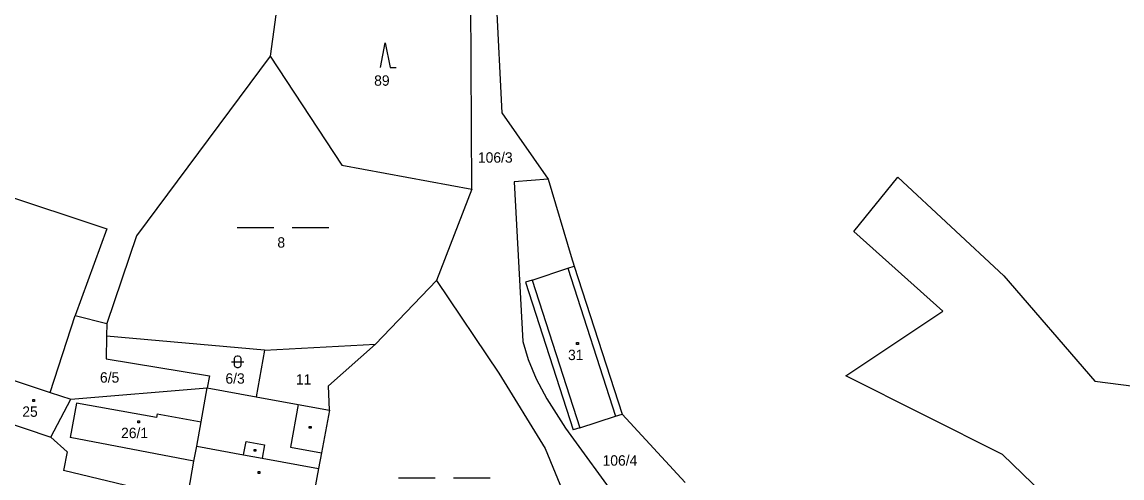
# Model space of a CAD drawing. Extents: x -794421 to -792735, y -1117671 to -1115559.
# Drawn here: x -793289.6 to -793109.5, y -1116924 to -1116849.4 of the extents above; entities that cross this region are included whole.
import ezdxf

# ---------------------------------------------------------------- set-up
doc = ezdxf.new("R2010")
doc.units = 0
for name, color, linetype in [('Vrstva 1', 7, 'Continuous'), ('Vrstva 14', 7, 'Continuous'), ('Vrstva 15', 7, 'Continuous'), ('Vrstva 2', 7, 'Continuous'), ('Vrstva 23', 7, 'Continuous'), ('Vrstva 25', 7, 'Continuous')]:
    doc.layers.add(name, color=color, linetype=linetype)

msp = doc.modelspace()

# ---------------------------------------------------------------- linework, layer by layer
at = {"layer": 'Vrstva 1'}
for p, q in [((-793246.16, -1116834.96), (-793248.94, -1116854.97)), ((-793215.92, -1116876.71), (-793216.07, -1116845.94)), ((-793211.95, -1116845.79), (-793211, -1116864.23)), ((-793248.94, -1116854.97), (-793270.84, -1116884.36)), ((-793248.94, -1116854.97), (-793237.19, -1116872.8)), ((-793211, -1116864.23), (-793203.41, -1116875.06)), ((-793237.19, -1116872.8), (-793215.92, -1116876.71)), ((-793299.01, -1116875.45), (-793275.69, -1116883.23)), ((-793203.41, -1116875.06), (-793208.97, -1116875.53)), ((-793208.97, -1116875.53), (-793207.6, -1116901.62)), ((-793203.41, -1116875.06), (-793199.69, -1116887.74)), ((-793153.39, -1116883.62), (-793146.19, -1116874.73)), ((-793146.19, -1116874.73), (-793128.82, -1116890.9)), ((-793215.92, -1116876.71), (-793221.71, -1116891.66)), ((-793275.69, -1116883.23), (-793280.87, -1116897.4)), ((-793270.84, -1116884.36), (-793275.7, -1116898.71)), ((-793138.84, -1116896.68), (-793153.39, -1116883.62)), ((-793199.69, -1116887.74), (-793199.16, -1116889.31)), ((-793206.04, -1116891.58), (-793200.23, -1116889.66)), ((-793200.23, -1116889.66), (-793199.16, -1116889.31)), ((-793199.16, -1116889.31), (-793191.3, -1116913.51)), ((-793231.72, -1116902.1), (-793221.71, -1116891.66)), ((-793221.71, -1116891.66), (-793211.52, -1116906.82)), ((-793206.04, -1116891.58), (-793207.13, -1116891.93)), ((-793128.82, -1116890.9), (-793113.92, -1116908.11)), ((-793207.13, -1116891.93), (-793199.32, -1116916.1)), ((-793154.73, -1116907.27), (-793138.84, -1116896.68)), ((-793284.93, -1116909.98), (-793280.87, -1116897.4)), ((-793280.87, -1116897.4), (-793275.7, -1116898.71)), ((-793275.7, -1116898.71), (-793275.72, -1116900.76)), ((-793275.72, -1116900.76), (-793275.77, -1116904.46)), ((-793249.88, -1116903.07), (-793275.72, -1116900.76)), ((-793249.88, -1116903.07), (-793231.72, -1116902.1)), ((-793239.38, -1116908.89), (-793231.72, -1116902.1)), ((-793207.6, -1116901.62), (-793206.71, -1116904.59)), ((-793249.88, -1116903.07), (-793251.24, -1116910.68)), ((-793275.77, -1116904.46), (-793258.87, -1116907.25)), ((-793206.71, -1116904.59), (-793205.4, -1116907.72)), ((-793290.84, -1116908.04), (-793284.93, -1116909.98)), ((-793258.87, -1116907.25), (-793259.23, -1116909.22)), ((-793211.52, -1116906.82), (-793203.93, -1116919.16)), ((-793205.4, -1116907.72), (-793203.65, -1116911.03)), ((-793129.06, -1116920.12), (-793154.73, -1116907.27)), ((-793281.59, -1116911.07), (-793259.23, -1116909.22)), ((-793260.24, -1116914.78), (-793259.23, -1116909.22)), ((-793259.23, -1116909.22), (-793251.24, -1116910.68)), ((-793239.22, -1116912.89), (-793239.38, -1116908.89)), ((-793113.92, -1116908.11), (-793098.62, -1116910.09)), ((-793284.93, -1116909.98), (-793281.59, -1116911.07)), ((-793284.83, -1116917.28), (-793281.59, -1116911.07)), ((-793251.24, -1116910.68), (-793244.33, -1116911.95)), ((-793203.65, -1116911.03), (-793200.57, -1116915.82)), ((-793244.33, -1116911.95), (-793239.22, -1116912.89)), ((-793239.22, -1116912.89), (-793240.52, -1116919.87)), ((-793294.01, -1116914.2), (-793284.83, -1116917.28)), ((-793260.96, -1116918.75), (-793260.24, -1116914.78)), ((-793198.23, -1116915.75), (-793192.39, -1116913.86)), ((-793192.39, -1116913.86), (-793191.3, -1116913.51)), ((-793180.98, -1116924.73), (-793191.3, -1116913.51)), ((-793200.57, -1116915.82), (-793190.84, -1116929.15)), ((-793198.23, -1116915.75), (-793199.32, -1116916.1)), ((-793284.83, -1116917.28), (-793282.14, -1116919.69)), ((-793261.41, -1116921.2), (-793260.96, -1116918.75)), ((-793282.14, -1116919.69), (-793282.79, -1116922.72)), ((-793240.52, -1116919.87), (-793241, -1116922.43)), ((-793203.93, -1116919.16), (-793192.01, -1116947.74)), ((-793118.24, -1116930.56), (-793129.06, -1116920.12)), ((-793262.33, -1116926.27), (-793261.41, -1116921.2)), ((-793241, -1116922.43), (-793242.42, -1116930.04)), ((-793262.58, -1116927.59), (-793282.79, -1116922.72))]:
    msp.add_line(p, q, dxfattribs=at)
at = {"layer": 'Vrstva 2'}
for p, q in [((-793200.23, -1116889.66), (-793192.39, -1116913.86)), ((-793206.04, -1116891.58), (-793198.23, -1116915.75)), ((-793280.62, -1116911.72), (-793281.7, -1116917.37)), ((-793267.54, -1116914.09), (-793280.62, -1116911.72)), ((-793244.33, -1116911.95), (-793245.63, -1116918.93)), ((-793267.42, -1116913.47), (-793267.54, -1116914.09)), ((-793267.42, -1116913.47), (-793260.24, -1116914.78)), ((-793261.41, -1116921.2), (-793281.7, -1116917.37)), ((-793260.96, -1116918.75), (-793253.29, -1116920.16)), ((-793253.29, -1116920.16), (-793252.89, -1116918)), ((-793252.89, -1116918), (-793249.84, -1116918.56)), ((-793249.84, -1116918.56), (-793250.24, -1116920.72)), ((-793253.29, -1116920.16), (-793250.24, -1116920.72)), ((-793245.63, -1116918.93), (-793240.52, -1116919.87)), ((-793250.24, -1116920.72), (-793241, -1116922.43))]:
    msp.add_line(p, q, dxfattribs=at)
at = {"layer": 'Vrstva 23'}
for p, q in [((-793230.9, -1116856.79), (-793230.1, -1116852.79)), ((-793230.1, -1116852.79), (-793229.3, -1116856.79)), ((-793229.3, -1116856.79), (-793228.3, -1116856.79)), ((-793254.36, -1116882.99), (-793248.36, -1116882.99)), ((-793245.36, -1116882.99), (-793239.36, -1116882.99)), ((-793254.75, -1116904.36), (-793254.65, -1116904.16)), ((-793254.75, -1116905.56), (-793254.75, -1116904.36)), ((-793254.65, -1116904.16), (-793254.55, -1116904.06)), ((-793254.55, -1116904.06), (-793254.35, -1116903.96)), ((-793254.35, -1116903.96), (-793254.15, -1116903.96)), ((-793254.15, -1116903.96), (-793253.95, -1116904.06)), ((-793253.95, -1116904.06), (-793253.85, -1116904.16)), ((-793253.85, -1116904.16), (-793253.75, -1116904.36)), ((-793253.75, -1116904.36), (-793253.75, -1116905.56)), ((-793255.25, -1116904.96), (-793253.25, -1116904.96)), ((-793254.65, -1116905.76), (-793254.75, -1116905.56)), ((-793254.55, -1116905.86), (-793254.65, -1116905.76)), ((-793254.35, -1116905.96), (-793254.55, -1116905.86)), ((-793254.15, -1116905.96), (-793254.35, -1116905.96)), ((-793253.95, -1116905.86), (-793254.15, -1116905.96)), ((-793253.85, -1116905.76), (-793253.95, -1116905.86)), ((-793253.75, -1116905.56), (-793253.85, -1116905.76)), ((-793227.94, -1116923.94), (-793221.94, -1116923.94)), ((-793218.94, -1116923.94), (-793212.94, -1116923.94))]:
    msp.add_line(p, q, dxfattribs=at)
at = {"layer": 'Vrstva 25'}
for p, q in [((-793198.77, -1116901.82), (-793198.47, -1116901.82)), ((-793198.77, -1116902.12), (-793198.77, -1116901.82)), ((-793198.47, -1116902.12), (-793198.77, -1116902.12)), ((-793198.47, -1116901.82), (-793198.47, -1116902.12)), ((-793287.81, -1116911.13), (-793287.51, -1116911.13)), ((-793287.81, -1116911.43), (-793287.81, -1116911.13)), ((-793287.51, -1116911.43), (-793287.81, -1116911.43)), ((-793287.51, -1116911.13), (-793287.51, -1116911.43)), ((-793270.61, -1116914.64), (-793270.31, -1116914.64)), ((-793270.61, -1116914.94), (-793270.61, -1116914.64)), ((-793270.31, -1116914.94), (-793270.61, -1116914.94)), ((-793270.31, -1116914.64), (-793270.31, -1116914.94)), ((-793242.53, -1116915.54), (-793242.23, -1116915.54)), ((-793242.53, -1116915.84), (-793242.53, -1116915.54)), ((-793242.23, -1116915.84), (-793242.53, -1116915.84)), ((-793242.23, -1116915.54), (-793242.23, -1116915.84)), ((-793251.57, -1116919.29), (-793251.27, -1116919.29)), ((-793251.57, -1116919.59), (-793251.57, -1116919.29)), ((-793251.27, -1116919.59), (-793251.57, -1116919.59)), ((-793251.27, -1116919.29), (-793251.27, -1116919.59)), ((-793250.92, -1116922.91), (-793250.62, -1116922.91)), ((-793250.92, -1116923.21), (-793250.92, -1116922.91)), ((-793250.62, -1116923.21), (-793250.92, -1116923.21)), ((-793250.62, -1116922.91), (-793250.62, -1116923.21))]:
    msp.add_line(p, q, dxfattribs=at)

# ---------------------------------------------------------------- texts
at = {"layer": 'Vrstva 14'}
for s, p in [('89', (-793231.917, -1116859.79)), ('106/3', (-793214.932, -1116872.38)), ('8', (-793247.757, -1116886.28)), ('6/5', (-793276.797, -1116908.37)), ('6/3', (-793256.26, -1116908.54)), ('11', (-793244.723, -1116908.69)), ('106/4', (-793194.528, -1116921.95))]:
    msp.add_text(s, height=1.7, dxfattribs=at).set_placement(p)
at = {"layer": 'Vrstva 15'}
for s, p in [('31', (-793200.18, -1116904.68)), ('25', (-793289.513, -1116913.96)), ('26/1', (-793273.343, -1116917.45))]:
    msp.add_text(s, height=1.7, dxfattribs=at).set_placement(p)

doc.saveas('drawing.dxf')
